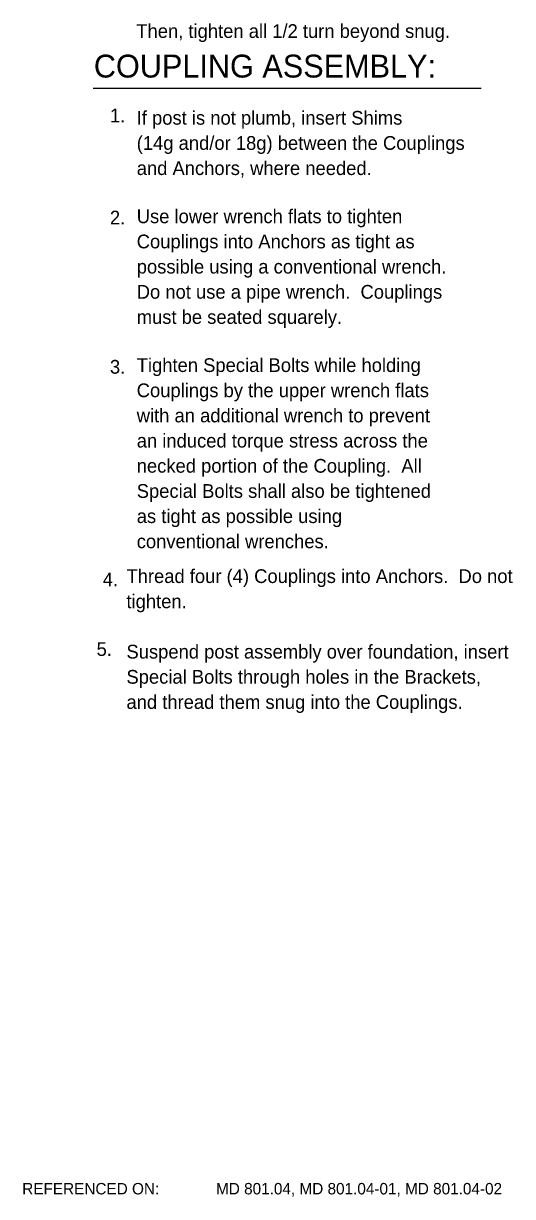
# Model space of a CAD drawing. Extents: x 12.3 to 19.6, y 5.9 to 16.2.
# Drawn here: x 12.25 to 14.39, y 5.85 to 10.98 of the extents above; entities that cross this region are included whole.
import ezdxf

# ---------------------------------------------------------------- set-up
doc = ezdxf.new("R2010")
doc.units = 0
doc.layers.add('DETL-DIMS', color=7, linetype='Continuous')
doc.layers.add('DETL-NOTE', color=7, linetype='Continuous')

msp = doc.modelspace()

# ---------------------------------------------------------------- linework, layer by layer
at = {"layer": 'DETL-NOTE'}
msp.add_line((12.5595, 10.6956), (14.2526, 10.6956), dxfattribs=at)

# ---------------------------------------------------------------- texts
at = {"layer": 'DETL-DIMS'}
for s, p in [('REFERENCED ON:', (12.2495, 5.8614)), ('MD 801.04, MD 801.04-01, MD 801.04-02', (13.0954, 5.8614))]:
    msp.add_text(s, height=0.05, dxfattribs=at).set_placement(p)
at = {"layer": 'DETL-NOTE'}
for s, height, p in [('Then, tighten all 1/2 turn beyond snug.', 0.06, (12.7475, 10.9152)), ('COUPLING ASSEMBLY:', 0.1, (12.5621, 10.7421)), ('1.', 0.06, (12.6323, 10.546)), ('If post is not plumb, insert Shims ', 0.06, (12.7493, 10.5361)), ('(14g and/or 18g) between the Couplings ', 0.06, (12.7493, 10.4261)), ('and Anchors, where needed.', 0.06, (12.7493, 10.3161)), ('2.', 0.06, (12.6323, 10.1)), ('Use lower wrench flats to tighten ', 0.06, (12.7493, 10.1057)), ('Couplings into Anchors as tight as ', 0.06, (12.7493, 9.9957)), ('possible using a conventional wrench.  ', 0.06, (12.7493, 9.8857)), ('Do not use a pipe wrench.  Couplings ', 0.06, (12.7493, 9.7757)), ('must be seated squarely.', 0.06, (12.7493, 9.6657)), ('3.', 0.06, (12.6323, 9.448)), ('Tighten Special Bolts while holding ', 0.06, (12.7493, 9.4553)), ('Couplings by the upper wrench flats ', 0.06, (12.7493, 9.3453)), ('with an additional wrench to prevent ', 0.06, (12.7493, 9.2353)), ('an induced torque stress across the ', 0.06, (12.7493, 9.1253)), ('necked portion of the Coupling.  All ', 0.06, (12.7493, 9.0153)), ('Special Bolts shall also be tightened ', 0.06, (12.7493, 8.9053)), ('as tight as possible using ', 0.06, (12.7493, 8.7953)), ('conventional wrenches.', 0.06, (12.7493, 8.6853)), ('4.', 0.06, (12.601, 8.5191)), ('Thread four (4) Couplings into Anchors.  Do not ', 0.06, (12.7045, 8.5332)), ('tighten.', 0.06, (12.7045, 8.4232)), ('5.', 0.06, (12.5741, 8.2144)), ('Suspend post assembly over foundation, insert ', 0.06, (12.7045, 8.2032)), ('Special Bolts through holes in the Brackets, ', 0.06, (12.7045, 8.0932)), ('and thread them snug into the Couplings.', 0.06, (12.7045, 7.9832))]:
    msp.add_text(s, height=height, dxfattribs=at).set_placement(p)

doc.saveas('drawing.dxf')
